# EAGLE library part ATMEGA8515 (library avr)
MICROCONTROLLER 8 Kbytes FLASH 512 bytes SRAM 512 bytes EEPROM USART
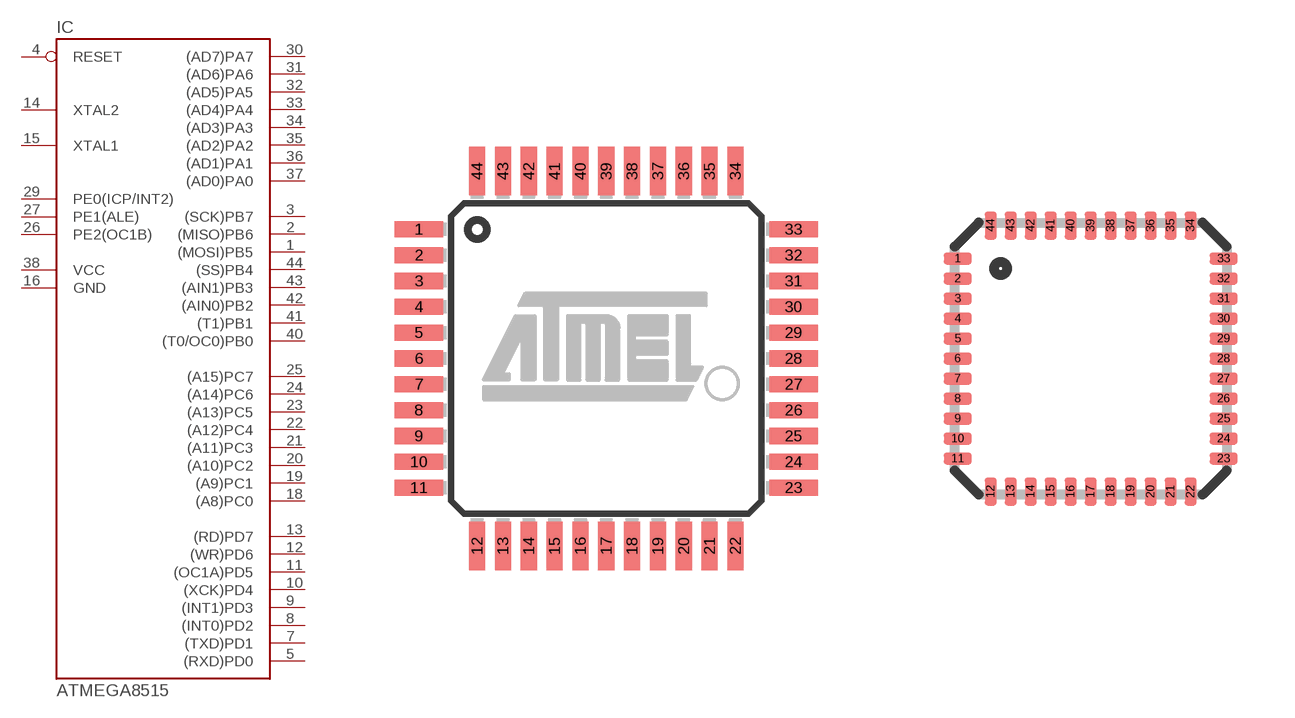
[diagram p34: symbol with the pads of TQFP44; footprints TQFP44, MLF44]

Designator prefix IC

## ATMEGA8515-16A, ATMEGA8515L-8A  [TQFP44]
1  (MOSI)PB5
2  (MISO)PB6
3  (SCK)PB7
4  RESET  in
5  (RXD)PD0
6  NC1  nc
7  (TXD)PD1
8  (INT0)PD2
9  (INT1)PD3
10  (XCK)PD4
11  (OC1A)PD5
12  (WR)PD6
13  (RD)PD7
14  XTAL2
15  XTAL1
16  GND  pwr
17  NC2  nc
18  (A8)PC0
19  (A9)PC1
20  (A10)PC2
21  (A11)PC3
22  (A12)PC4
23  (A13)PC5
24  (A14)PC6
25  (A15)PC7
26  PE2(OC1B)
27  PE1(ALE)
28  NC3  nc
29  PE0(ICP/INT2)
30  (AD7)PA7
31  (AD6)PA6
32  (AD5)PA5
33  (AD4)PA4
34  (AD3)PA3
35  (AD2)PA2
36  (AD1)PA1
37  (AD0)PA0
38  VCC  pwr
39  NC4  nc
40  (T0/OC0)PB0
41  (T1)PB1
42  (AIN0)PB2
43  (AIN1)PB3
44  (SS)PB4

## ATMEGA8515-16M, ATMEGA8515L-8M  [MLF44]
Pads as for TQFP44

## ATMEGA8515-16J, ATMEGA8515L-8J  [PLCC44]
1  NC1  nc
2  (T0/OC0)PB0
3  (T1)PB1
4  (AIN0)PB2
5  (AIN1)PB3
6  (SS)PB4
7  (MOSI)PB5
8  (MISO)PB6
9  (SCK)PB7
10  RESET  in
11  (RXD)PD0
12  NC2  nc
13  (TXD)PD1
14  (INT0)PD2
15  (INT1)PD3
16  (XCK)PD4
17  (OC1A)PD5
18  (WR)PD6
19  (RD)PD7
20  XTAL2
21  XTAL1
22  GND  pwr
23  NC3  nc
24  (A8)PC0
25  (A9)PC1
26  (A10)PC2
27  (A11)PC3
28  (A12)PC4
29  (A13)PC5
30  (A14)PC6
31  (A15)PC7
32  PE2(OC1B)
33  PE1(ALE)
34  NC4  nc
35  PE0(ICP/INT2)
36  (AD7)PA7
37  (AD6)PA6
38  (AD5)PA5
39  (AD4)PA4
40  (AD3)PA3
41  (AD2)PA2
42  (AD1)PA1
43  (AD0)PA0
44  VCC  pwr

## ATMEGA8515-16J-SMD, ATMEGA8515L-8J-SMD  [PLCC-SM44]
Pads as for PLCC44

## ATMEGA8515-16J-SO, ATMEGA8515L-8J-SO  [S44]
Pads as for PLCC44

## Footprint TQFP44 (pad centres in mm)
Thin Plasic Quad Flat Package
smd 1.5 x 0.5: 1 -5.8,4; 2 -5.8,3.2; 3 -5.8,2.4; 4 -5.8,1.6; 5 -5.8,0.8; 6 -5.8,0; 7 -5.8,-0.8; 8 -5.8,-1.6; 9 -5.8,-2.4; 10 -5.8,-3.2; 11 -5.8,-4; 23 5.8,-4; 24 5.8,-3.2; 25 5.8,-2.4; 26 5.8,-1.6; 27 5.8,-0.8; 28 5.8,0; 29 5.8,0.8; 30 5.8,1.6; 31 5.8,2.4; 32 5.8,3.2; 33 5.8,4
smd 0.5 x 1.5: 12 -4,-5.8; 13 -3.2,-5.8; 14 -2.4,-5.8; 15 -1.6,-5.8; 16 -0.8,-5.8; 17 0,-5.8; 18 0.8,-5.8; 19 1.6,-5.8; 20 2.4,-5.8; 21 3.2,-5.8; 22 4,-5.8; 34 4,5.8; 35 3.2,5.8; 36 2.4,5.8; 37 1.6,5.8; 38 0.8,5.8; 39 0,5.8; 40 -0.8,5.8; 41 -1.6,5.8; 42 -2.4,5.8; 43 -3.2,5.8; 44 -4,5.8

## Footprint MLF44 (pad centres in mm)
44M1 Micro Lead Frame package (MLF)
smd 0.7 x 0.3: 1 -3.325,2.5; 2 -3.325,2; 3 -3.325,1.5; 4 -3.325,1; 5 -3.325,0.5; 6 -3.325,0; 7 -3.325,-0.5; 8 -3.325,-1; 9 -3.325,-1.5; 10 -3.325,-2; 11 -3.325,-2.5; 23 3.325,-2.5; 24 3.325,-2; 25 3.325,-1.5; 26 3.325,-1; 27 3.325,-0.5; 28 3.325,0; 29 3.325,0.5; 30 3.325,1; 31 3.325,1.5; 32 3.325,2; 33 3.325,2.5
smd 0.3 x 0.7: 12 -2.5,-3.325; 13 -2,-3.325; 14 -1.5,-3.325; 15 -1,-3.325; 16 -0.5,-3.325; 17 0,-3.325; 18 0.5,-3.325; 19 1,-3.325; 20 1.5,-3.325; 21 2,-3.325; 22 2.5,-3.325; 34 2.5,3.325; 35 2,3.325; 36 1.5,3.325; 37 1,3.325; 38 0.5,3.325; 39 0,3.325; 40 -0.5,3.325; 41 -1,3.325; 42 -1.5,3.325; 43 -2,3.325; 44 -2.5,3.325

## Footprint PLCC44 (pad centres in mm)
Plastic J-Leaded Chip Carrier
smd 1.8 x 0.76: 1 -7.86,0; 2 -7.86,-1.27; 3 -7.86,-2.54; 4 -7.86,-3.81; 5 -7.86,-5.08; 6 -7.86,-6.35; 18 7.86,-6.35; 19 7.86,-5.08; 20 7.86,-3.81; 21 7.86,-2.54; 22 7.86,-1.27; 23 7.86,0; 24 7.86,1.27; 25 7.86,2.54; 26 7.86,3.81; 27 7.86,5.08; 28 7.86,6.35; 40 -7.86,6.35; 41 -7.86,5.08; 42 -7.86,3.81; 43 -7.86,2.54; 44 -7.86,1.27
smd 0.76 x 1.8: 7 -6.35,-7.86; 8 -5.08,-7.86; 9 -3.81,-7.86; 10 -2.54,-7.86; 11 -1.27,-7.86; 12 0,-7.86; 13 1.27,-7.86; 14 2.54,-7.86; 15 3.81,-7.86; 16 5.08,-7.86; 17 6.35,-7.86; 29 6.35,7.86; 30 5.08,7.86; 31 3.81,7.86; 32 2.54,7.86; 33 1.27,7.86; 34 0,7.86; 35 -1.27,7.86; 36 -2.54,7.86; 37 -3.81,7.86; 38 -5.08,7.86; 39 -6.35,7.86

## Footprint PLCC-SM44 (pad centres in mm)
SMD Plastic J-Leaded Chip Carrier Socket
smd 2.591 x 0.66: 1 -8.89,0; 2 -8.89,-1.27; 3 -8.89,-2.54; 4 -8.89,-3.81; 5 -8.89,-5.08; 6 -8.89,-6.35; 18 8.89,-6.35; 19 8.89,-5.08; 20 8.89,-3.81; 21 8.89,-2.54; 22 8.89,-1.27; 23 8.89,0; 24 8.89,1.27; 25 8.89,2.54; 26 8.89,3.81; 27 8.89,5.08; 28 8.89,6.35; 40 -8.89,6.35; 41 -8.89,5.08; 42 -8.89,3.81; 43 -8.89,2.54; 44 -8.89,1.27
smd 0.66 x 2.591: 7 -6.35,-8.89; 8 -5.08,-8.89; 9 -3.81,-8.89; 10 -2.54,-8.89; 11 -1.27,-8.89; 12 0,-8.89; 13 1.27,-8.89; 14 2.54,-8.89; 15 3.81,-8.89; 16 5.08,-8.89; 17 6.35,-8.89; 29 6.35,8.89; 30 5.08,8.89; 31 3.81,8.89; 32 2.54,8.89; 33 1.27,8.89; 34 0,9.017; 35 -1.27,8.89; 36 -2.54,8.89; 37 -3.81,8.89; 38 -5.08,8.89; 39 -6.35,8.89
